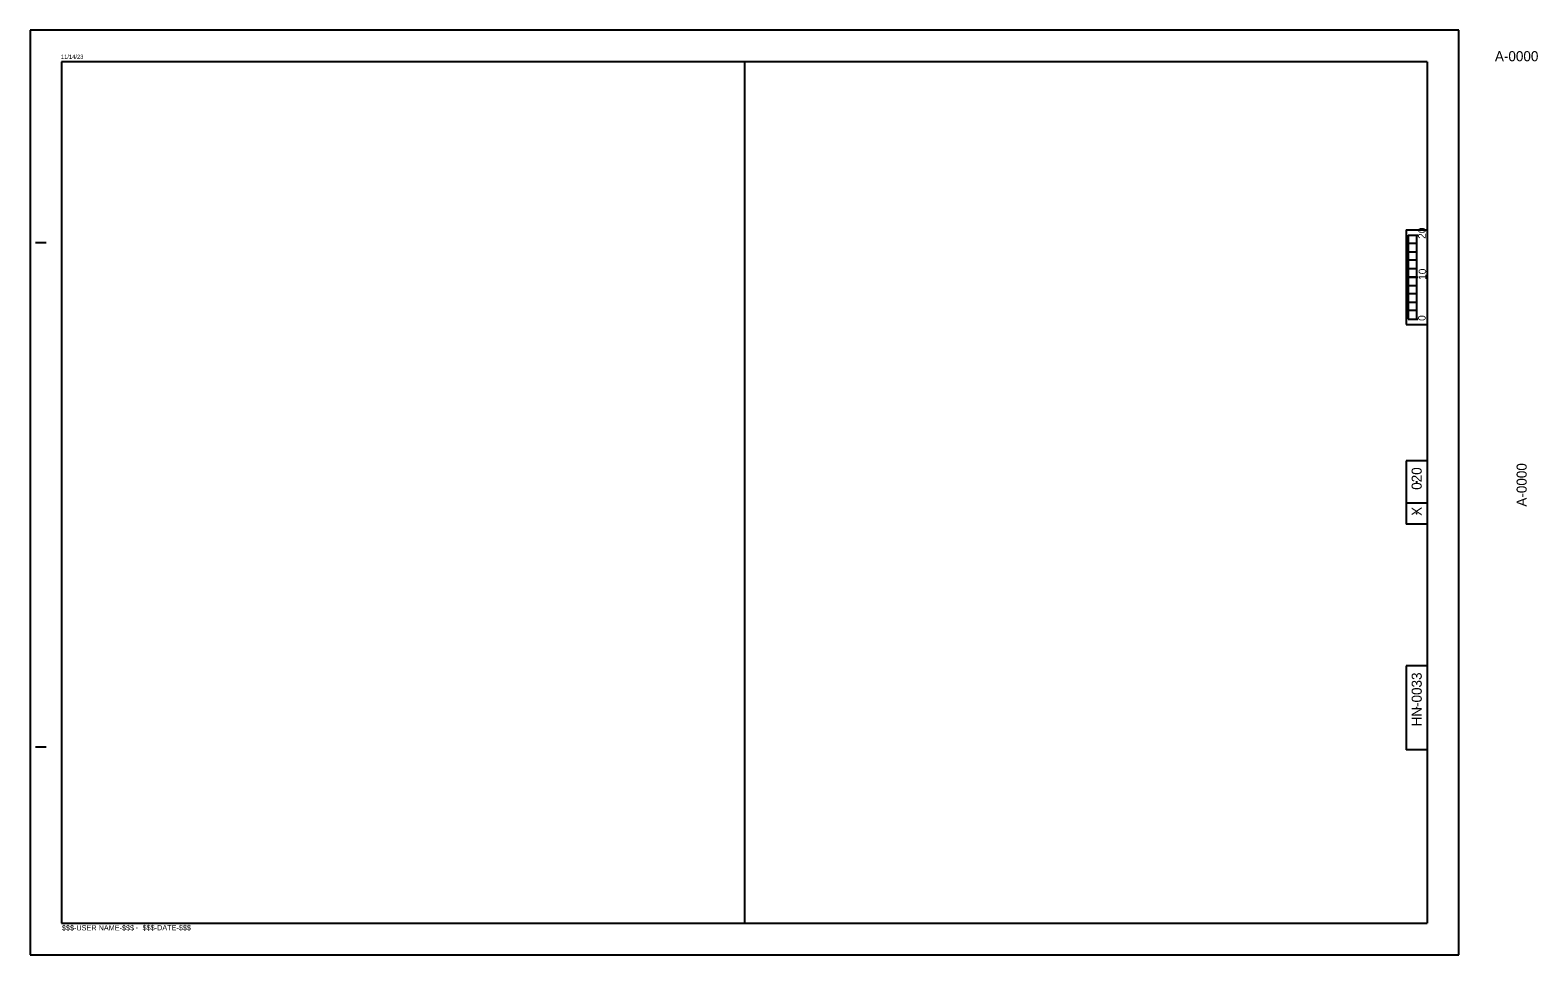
# Model space of a CAD drawing. Extents: x -2.69 to 2.99, y 0 to 1.83.
# Drawn here: x 0 to 2.99, y 0 to 1.833 of the extents above; entities that cross this region are included whole.
import ezdxf

# ---------------------------------------------------------------- set-up
doc = ezdxf.new("R2010")
doc.units = 0
for name, color, linetype in [('_CIVIL_CONSTRUCTION', 7, 'Continuous'), ('P_NCDOT_XS_Label_Finished_Grade', 7, 'Continuous'), ('P_NCDOT_XS_Label_Grade_Point', 7, 'Continuous'), ('P_NCDOT_XS_Leader_Line', 7, 'Continuous'), ('P_NCDOT_XS_Sheet_Alignment_Station_Label', 7, 'Continuous')]:
    doc.layers.add(name, color=color, linetype=linetype)

msp = doc.modelspace()

# ---------------------------------------------------------------- linework, layer by layer
at = {"layer": 'P_NCDOT_XS_Label_Finished_Grade'}
for p, q in [((2.8333, 1.8333), (0, 1.8333)), ((0, 1.8333), (0, 0)), ((2.8333, 0), (2.8333, 1.8333)), ((1.4167, 1.7708), (1.4166, 0.0625)), ((0, 0), (2.8333, 0))]:
    msp.add_line(p, q, dxfattribs=at)
for centre in [(2.7499, 1.3437), (2.7499, 0.9375), (2.7499, 0.875), (2.75, 0.4897)]:
    msp.add_circle(centre, 0.0001, dxfattribs=at)
at = {"layer": 'P_NCDOT_XS_Label_Grade_Point'}
for p, q in [((2.7332, 1.4272), (2.7521, 1.4272)), ((2.7332, 1.4272), (2.7332, 1.2605)), ((2.7416, 1.4272), (2.7503, 1.4272)), ((2.7499, 1.4272), (2.7499, 1.2605)), ((2.7332, 1.3438), (2.7521, 1.3438)), ((2.7332, 1.2605), (2.7521, 1.2605)), ((2.7416, 1.2605), (2.7503, 1.2605))]:
    msp.add_line(p, q, dxfattribs=at)
for points in [[(2.7332, 1.4272), (2.7499, 1.4272), (2.7499, 1.4105), (2.7332, 1.4105)], [(2.7332, 1.3938), (2.7499, 1.3938), (2.7499, 1.3772), (2.7332, 1.3772)], [(2.7332, 1.3605), (2.7499, 1.3605), (2.7499, 1.3438), (2.7332, 1.3438)], [(2.7332, 1.3272), (2.7499, 1.3272), (2.7499, 1.3105), (2.7332, 1.3105)], [(2.7332, 1.2938), (2.7499, 1.2938), (2.7499, 1.2772), (2.7332, 1.2772)]]:
    msp.add_lwpolyline(points, close=True, dxfattribs=at)
at = {"layer": 'P_NCDOT_XS_Leader_Line'}
for p, q in [((0.0625, 1.7708), (0.0625, 0.0625)), ((2.7708, 1.7708), (0.0625, 1.7708)), ((0.1027, 1.7844), (0.1027, 1.7844)), ((2.7708, 1.7708), (2.7708, 0.0625)), ((2.7292, 1.4375), (2.7292, 1.25)), ((2.7292, 1.4375), (2.7708, 1.4375)), ((0.0108, 1.4125), (0.0317, 1.4126)), ((2.7292, 1.25), (2.7708, 1.25)), ((2.7292, 0.9792), (2.7292, 0.8542)), ((2.7708, 0.9792), (2.7292, 0.9792)), ((2.7708, 0.8958), (2.7292, 0.8958)), ((2.7708, 0.8542), (2.7292, 0.8542)), ((2.7292, 0.5729), (2.7292, 0.4062)), ((2.7708, 0.5729), (2.7292, 0.5729)), ((0.0109, 0.4125), (0.0317, 0.4125)), ((2.7708, 0.4062), (2.7292, 0.4062)), ((0.0625, 0.0625), (2.7708, 0.0625))]:
    msp.add_line(p, q, dxfattribs=at)

# ---------------------------------------------------------------- texts
at = {"layer": '_CIVIL_CONSTRUCTION'}
for s, p in [('020', (2.7599, 0.922)), ('X', (2.7599, 0.8704))]:
    msp.add_text(s, height=0.02, rotation=90, dxfattribs=at).set_placement(p)
at = {"layer": 'P_NCDOT_XS_Label_Grade_Point'}
for s, p in [('20', (2.7678, 1.4196)), ('10', (2.7688, 1.3382)), ('0', (2.7677, 1.2569))]:
    msp.add_text(s, height=0.015, rotation=90, dxfattribs=at).set_placement(p)
at = {"layer": 'P_NCDOT_XS_Leader_Line'}
msp.add_text('11/14/23', height=0.00833, rotation=0, dxfattribs=at).set_placement((0.0609, 1.7764))
for s, height, p in [('$$$-DATE-$$$', 0.010417, (0.223, 0.0486)), ('$$$-USER NAME-$$$', 0.010417, (0.063, 0.0484)), ('-', 0.0104, (0.2093, 0.0494))]:
    msp.add_text(s, height=height, dxfattribs=at).set_placement(p)
at = {"layer": 'P_NCDOT_XS_Sheet_Alignment_Station_Label'}
msp.add_text('A-0000', height=0.02, dxfattribs=at).set_placement((2.9051, 1.7717))
for s, p in [('A-0000', (2.9681, 0.8886)), ('HN-0033', (2.76, 0.4528))]:
    msp.add_text(s, height=0.02, rotation=90, dxfattribs=at).set_placement(p)

doc.saveas('drawing.dxf')
